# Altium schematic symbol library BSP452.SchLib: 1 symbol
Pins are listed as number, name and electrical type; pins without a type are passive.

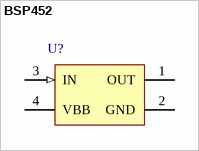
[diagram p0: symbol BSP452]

## BSP452
designator U?
Smart High-Side Power Switch, 1 Channel, 0.7 A Load Current, -40 to 150 degC, PG-SOT223_SC-73, Reel, Green; Manufacturer: Infineon; PartNumber: BSP452; Channels: 1; Green: TRUE; Group: Automotive Qualified; Load Current (typ): 0.7 A; Ptot (max): 1.8 W; Recommended Operating Voltage Max.: 34 V; Recommended Operating Voltage Min.: 5 V; RON @ 25degreesC: 200 mOhm; RON(max) @ 150degreesC: 400 mOhm; toff (max): 150 us; ton (max): 100 us
footprint INF-PG-SOT-223_N (SOT223, 4-Leads, Body 6.5x3.5mm, Pitch 2.3mm, IPC Medium Density)
footprint INF-PG-SOT-223_L (SOT223, 4-Leads, Body 6.5x3.5mm, Pitch 2.3mm, IPC High Density)
footprint INF-PG-SOT-223_M (SOT223, 4-Leads, Body 6.5x3.5mm, Pitch 2.3mm, IPC Low Density)
pins: 1 OUT (power) "Output to the load", 2 GND (power) "Logic ground", 3 IN (in) "Input, activates the power switch in case of logical high signal", 4 VBB (power) "Positive power supply voltage"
